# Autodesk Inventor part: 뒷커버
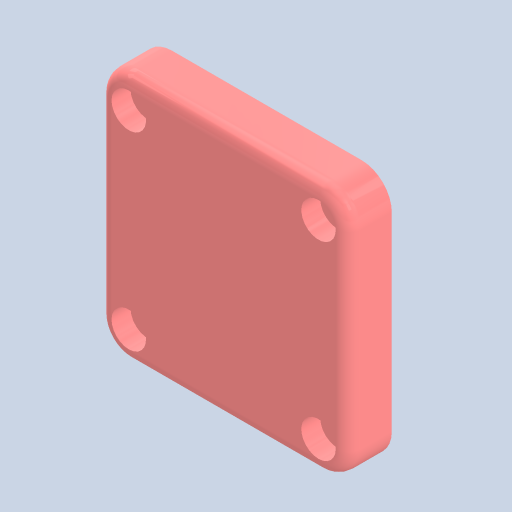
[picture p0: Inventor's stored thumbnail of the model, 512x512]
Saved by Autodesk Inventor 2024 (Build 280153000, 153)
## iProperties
Created: 2026-01
Part Number: 뒷커버
Material: 알루미늄 6061
Document SubType Name: Modeling
Designer: 2-10
Density: 2.7 g/cm^3
Appearance: 기본값
Author: jhkim
Sending System: Autodesk Inventor 2026
Preprocessor: ST-DEVELOPER v20.1
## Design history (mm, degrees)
feature "솔리드1"
node "솔리드2"
